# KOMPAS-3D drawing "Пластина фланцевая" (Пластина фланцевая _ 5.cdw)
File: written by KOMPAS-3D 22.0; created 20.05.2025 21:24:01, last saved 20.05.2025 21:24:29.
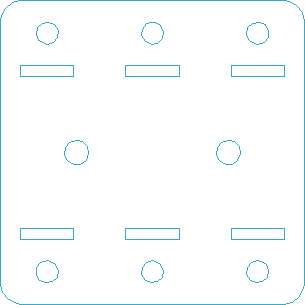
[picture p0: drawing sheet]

Sheet 1: A4, portrait

Document properties: Автор: TC; Масса: 0.815547; Полное имя файла: Пластина фланцевая.m3d

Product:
- Part/product: Пластина фланцевая
    Масса: 0.815547
    Форматы листов документа: A4

Title block, sheet 1: Наименование: Пластина / фланцевая; Материал: Сталь 10 ГОСТ 1050-2013; Масса: 0,82; Количество листов документа: 1; Форматы листов документа: A4

Views: Вид 1, Сверху
Referenced files in D:\Работа\2025\5. Май\Задание №6 - Тележка для крыши\3Д\Узел монтажный\: Пластина фланцевая.m3d
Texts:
  Без оформления
Dimensions and other numbers on the sheet: 1:1; 1; 0,82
